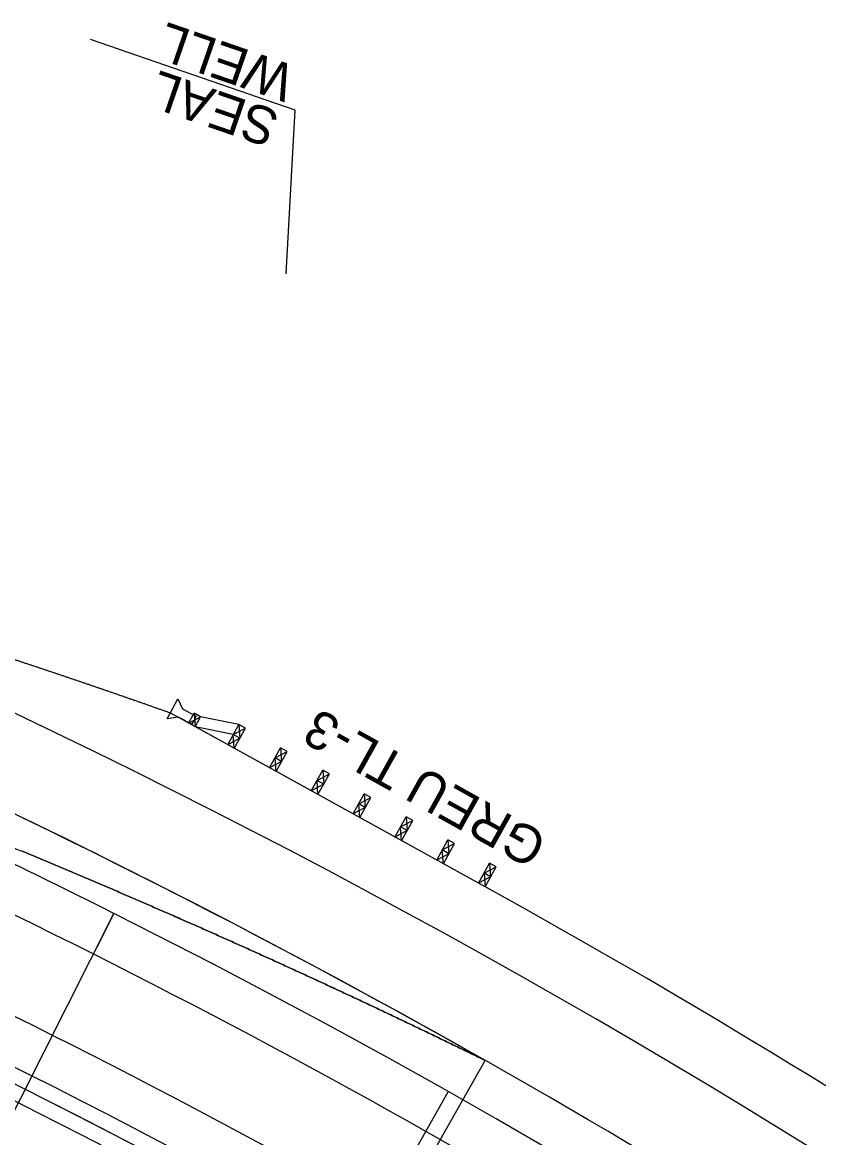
# Model space of a CAD drawing. Extents: x 472216 to 481979, y 489069 to 507339.
# Drawn here: x 480620.5 to 480725.5, y 493203.9 to 493351.1 of the extents above; entities that cross this region are included whole.
import ezdxf

# ---------------------------------------------------------------- set-up
doc = ezdxf.new("R2010")
doc.units = 0
for name, color, linetype in [('Exist Structure Minor Pipes HDPE 12 Inch Text', 7, 'Continuous'), ('Prop Drainage Structure Pipe CSP 15in', 7, 'Continuous'), ('Prop Drainage Structure Pipe Plug CELL', 7, 'Continuous'), ('Prop Drainage Structure Pipe RCP 15in Class III Label', 7, 'Continuous'), ('Prop Drainage Structure Pipe RCP 24in Class III Label', 7, 'Continuous'), ('Prop Drainage Structure Tops and Inverts LABEL', 7, 'Continuous'), ('Prop Erosion Embankment Toe Protection CELL', 7, 'Continuous'), ('Sheet Block Revision CELL', 7, 'Continuous'), ('Sheet Clip Boundary CELL', 7, 'Continuous'), ('Sheet North Arrow Point CELL', 7, 'Continuous'), ('Sheet PE Seal Cell', 7, 'Continuous')]:
    doc.layers.add(name, color=color, linetype=linetype)

msp = doc.modelspace()

# ---------------------------------------------------------------- linework, layer by layer
at = {"layer": 'Exist Structure Minor Pipes HDPE 12 Inch Text'}
msp.add_arc((480155.24, 492284.78), 1036, 57.51935, 71.25998, dxfattribs=at)
at = {"layer": 'Prop Drainage Structure Pipe Plug CELL'}
for p, q in [((480639.59, 493259.17), (480640.97, 493261.77)), ((480640.97, 493261.77), (480641.61, 493260.46)), ((480641.61, 493260.46), (480643.42, 493259.51)), ((480642.4, 493258.59), (480643.13, 493259.9)), ((480644, 493259.42), (480643.13, 493259.9)), ((480643.13, 493259.9), (480643.28, 493258.1)), ((480641.04, 493259.38), (480639.59, 493259.17)), ((480642.85, 493258.43), (480641.04, 493259.38)), ((480642.4, 493258.59), (480644, 493259.42)), ((480683.76, 493235.74), (480642.84, 493258.34)), ((480643.13, 493258.97), (480642.85, 493258.43)), ((480643.42, 493259.51), (480643.13, 493258.97)), ((480643.28, 493258.1), (480644, 493259.42)), ((480644, 493259.42), (480643.56, 493259.66)), ((480649.05, 493258.42), (480644, 493259.42)), ((480647.57, 493255.73), (480649.05, 493258.42)), ((480649.92, 493257.93), (480649.05, 493258.42)), ((480649.05, 493258.42), (480649.18, 493256.59)), ((480648.31, 493257.07), (480643.28, 493258.1)), ((480648.31, 493257.07), (480649.92, 493257.93)), ((480649.18, 493256.59), (480648.31, 493257.07)), ((480648.44, 493255.25), (480648.31, 493257.07)), ((480648.44, 493255.25), (480649.92, 493257.93)), ((480649.18, 493256.59), (480647.57, 493255.73)), ((480653.08, 493252.69), (480654.53, 493255.31)), ((480653.81, 493254), (480655.41, 493254.83)), ((480654.68, 493253.52), (480653.81, 493254)), ((480653.96, 493252.2), (480653.81, 493254)), ((480653.96, 493252.2), (480655.41, 493254.83)), ((480655.41, 493254.83), (480654.53, 493255.31)), ((480654.53, 493255.31), (480654.68, 493253.52)), ((480654.68, 493253.52), (480653.08, 493252.69)), ((480658.6, 493249.64), (480660.12, 493252.39)), ((480659.36, 493251.01), (480660.99, 493251.9)), ((480660.23, 493250.53), (480659.36, 493251.01)), ((480659.47, 493249.16), (480659.36, 493251.01)), ((480659.47, 493249.16), (480660.99, 493251.9)), ((480660.99, 493251.9), (480660.12, 493252.39)), ((480660.12, 493252.39), (480660.23, 493250.53)), ((480660.23, 493250.53), (480658.6, 493249.64)), ((480664.11, 493246.59), (480665.58, 493249.25)), ((480664.85, 493247.92), (480666.46, 493248.77)), ((480664.99, 493246.11), (480666.46, 493248.77)), ((480666.46, 493248.77), (480665.58, 493249.25)), ((480665.58, 493249.25), (480665.72, 493247.44)), ((480665.72, 493247.44), (480664.11, 493246.59)), ((480664.99, 493246.11), (480664.11, 493246.59)), ((480665.72, 493247.44), (480664.85, 493247.92)), ((480664.99, 493246.11), (480664.85, 493247.92)), ((480669.63, 493243.55), (480671.1, 493246.22)), ((480670.37, 493244.88), (480671.98, 493245.73)), ((480670.51, 493243.06), (480671.98, 493245.73)), ((480671.98, 493245.73), (480671.1, 493246.22)), ((480671.1, 493246.22), (480671.24, 493244.4)), ((480671.24, 493244.4), (480669.63, 493243.55)), ((480671.24, 493244.4), (480670.37, 493244.88)), ((480670.51, 493243.06), (480670.37, 493244.88)), ((480675.15, 493240.5), (480676.62, 493243.17)), ((480675.88, 493241.84), (480677.5, 493242.69)), ((480676.02, 493240.02), (480677.5, 493242.69)), ((480677.5, 493242.69), (480676.62, 493243.17)), ((480676.62, 493243.17), (480676.76, 493241.35)), ((480676.76, 493241.35), (480675.15, 493240.5)), ((480676.76, 493241.35), (480675.88, 493241.84)), ((480676.02, 493240.02), (480675.88, 493241.84)), ((480680.66, 493237.46), (480682.11, 493240.08)), ((480681.39, 493238.77), (480682.99, 493239.6)), ((480681.54, 493236.97), (480682.99, 493239.6)), ((480682.99, 493239.6), (480682.11, 493240.08)), ((480682.11, 493240.08), (480682.26, 493238.29)), ((480680.66, 493237.46), (480681.39, 493238.77)), ((480682.26, 493238.29), (480680.66, 493237.46)), ((480682.26, 493238.29), (480681.39, 493238.77)), ((480681.39, 493238.77), (480681.54, 493236.97)), ((480681.54, 493236.97), (480680.66, 493237.46))]:
    msp.add_line(p, q, dxfattribs=at)
at = {"layer": 'Prop Drainage Structure Pipe RCP 15in Class III Label'}
for radius, start, end in [(1066, 50.82715, 71.26622), (1066, 60.45413, 71.26607), (1054, 50.82715, 71.26622)]:
    msp.add_arc((480155.89, 492286.67), radius, start, end, dxfattribs=at)
for points in [[(480599.82, 493249.96), (480600.36, 493249.75), (480601.2, 493249.43), (480602.04, 493249.1), (480602.88, 493248.77), (480603.72, 493248.43), (480604.56, 493248.1), (480605.4, 493247.77), (480606.24, 493247.44), (480607.08, 493247.1), (480607.92, 493246.77), (480608.76, 493246.43), (480609.6, 493246.1), (480610.43, 493245.76), (480611.27, 493245.42), (480612.11, 493245.08), (480612.95, 493244.74), (480613.79, 493244.4), (480614.62, 493244.06), (480615.46, 493243.72), (480616.3, 493243.38), (480617.13, 493243.03), (480617.97, 493242.69), (480618.8, 493242.35), (480619.64, 493242), (480620.48, 493241.66)], [(480681.55, 493214.05), (480680.74, 493214.45), (480679.92, 493214.85), (480679.11, 493215.24), (480678.29, 493215.64), (480677.47, 493216.04), (480676.66, 493216.43), (480675.84, 493216.83), (480675.02, 493217.22), (480674.21, 493217.62), (480673.39, 493218.01), (480672.57, 493218.4), (480671.75, 493218.79), (480670.93, 493219.18), (480670.12, 493219.57), (480669.3, 493219.96), (480668.48, 493220.35), (480667.66, 493220.74), (480666.84, 493221.13), (480666.02, 493221.51), (480665.2, 493221.9), (480664.38, 493222.28), (480663.55, 493222.67), (480662.73, 493223.05), (480661.91, 493223.43), (480661.09, 493223.82), (480660.27, 493224.2), (480659.44, 493224.58), (480658.62, 493224.96), (480657.8, 493225.34), (480656.98, 493225.72), (480656.15, 493226.09), (480655.33, 493226.47), (480654.5, 493226.85), (480653.68, 493227.22), (480652.85, 493227.6), (480652.03, 493227.97), (480651.2, 493228.35), (480650.38, 493228.72), (480649.55, 493229.09), (480648.73, 493229.46), (480647.9, 493229.83), (480647.07, 493230.2), (480646.25, 493230.57), (480645.42, 493230.94), (480644.59, 493231.31), (480643.76, 493231.68), (480642.93, 493232.04), (480642.11, 493232.41), (480641.28, 493232.77), (480640.45, 493233.14), (480639.62, 493233.5), (480638.79, 493233.86), (480637.96, 493234.22), (480637.13, 493234.58), (480636.3, 493234.95), (480635.47, 493235.31), (480634.64, 493235.66), (480633.81, 493236.02), (480632.98, 493236.38), (480632.15, 493236.74), (480631.31, 493237.09), (480630.48, 493237.45), (480629.65, 493237.8), (480628.82, 493238.16), (480627.98, 493238.51), (480627.15, 493238.86), (480626.32, 493239.21), (480625.48, 493239.57), (480624.65, 493239.92), (480623.82, 493240.26), (480622.98, 493240.61), (480622.15, 493240.96), (480621.31, 493241.31), (480620.48, 493241.66)], [(480620.48, 493241.66), (480621.31, 493241.31), (480622.15, 493240.96), (480622.98, 493240.61), (480623.82, 493240.26), (480624.65, 493239.92), (480625.48, 493239.57), (480626.32, 493239.21), (480627.15, 493238.86), (480627.98, 493238.51), (480628.82, 493238.16), (480629.65, 493237.8), (480630.48, 493237.45), (480631.31, 493237.09), (480632.15, 493236.74), (480632.98, 493236.38), (480633.81, 493236.02), (480634.64, 493235.66), (480635.47, 493235.31), (480636.3, 493234.95), (480637.13, 493234.58), (480637.96, 493234.22), (480638.79, 493233.86), (480639.62, 493233.5), (480640.45, 493233.14), (480641.03, 493232.88)], [(480641.03, 493232.88), (480641.28, 493232.77), (480642.11, 493232.41), (480642.93, 493232.04), (480643.76, 493231.68), (480644.59, 493231.31), (480645.42, 493230.94), (480646.25, 493230.57), (480647.07, 493230.2), (480647.9, 493229.83), (480648.73, 493229.46), (480649.55, 493229.09), (480650.38, 493228.72), (480651.2, 493228.35), (480652.03, 493227.97), (480652.85, 493227.6), (480653.68, 493227.22), (480654.5, 493226.85), (480655.33, 493226.47), (480656.15, 493226.09), (480656.98, 493225.72), (480657.8, 493225.34), (480658.62, 493224.96), (480659.44, 493224.58), (480660.27, 493224.2), (480661.09, 493223.82), (480661.39, 493223.68)], [(480661.39, 493223.68), (480661.91, 493223.43), (480662.73, 493223.05), (480663.55, 493222.67), (480664.38, 493222.28), (480665.2, 493221.9), (480666.02, 493221.51), (480666.84, 493221.13), (480667.66, 493220.74), (480668.48, 493220.35), (480669.3, 493219.96), (480670.12, 493219.57), (480670.93, 493219.18), (480671.75, 493218.79), (480672.57, 493218.4), (480673.39, 493218.01), (480674.21, 493217.62), (480675.02, 493217.22), (480675.84, 493216.83), (480676.66, 493216.43), (480677.47, 493216.04), (480678.29, 493215.64), (480679.11, 493215.24), (480679.92, 493214.85), (480680.74, 493214.45), (480681.55, 493214.05)]]:
    msp.add_spline(points, degree=3, dxfattribs=at)
at = {"layer": 'Prop Drainage Structure Pipe RCP 24in Class III Label'}
for radius, start, end in [(1078, 51.63222, 71.28205), (1042, 50.82715, 71.25998)]:
    msp.add_arc((480155.89, 492286.67), radius, start, end, dxfattribs=at)
at = {"layer": 'Prop Drainage Structure Tops and Inverts LABEL'}
for radius, start, end in [(1032, 47.5792, 71.2674), (1086, 51.63222, 60.91713)]:
    msp.add_arc((480155.89, 492286.67), radius, start, end, dxfattribs=at)
at = {"layer": 'Prop Erosion Embankment Toe Protection CELL'}
msp.add_line((480683.76, 493235.74), (480639.99, 493259.92), dxfattribs=at)
for radius, start, end in [(1036, 57.49364, 71.25998), (1086, 51.63222, 60.91713)]:
    msp.add_arc((480155.89, 492286.67), radius, start, end, dxfattribs=at)
msp.add_spline([(480639.99, 493259.92), (480639.57, 493260.07), (480639.15, 493260.22), (480638.72, 493260.36), (480638.3, 493260.51), (480637.88, 493260.66), (480637.46, 493260.81), (480637.04, 493260.96), (480636.62, 493261.11), (480636.2, 493261.25), (480635.77, 493261.4), (480635.35, 493261.55), (480634.93, 493261.69), (480634.51, 493261.84), (480634.09, 493261.99), (480633.67, 493262.13), (480633.24, 493262.28), (480632.82, 493262.43), (480632.4, 493262.57), (480631.98, 493262.72), (480631.56, 493262.86), (480631.14, 493263.01), (480630.71, 493263.15), (480630.29, 493263.3), (480629.87, 493263.44), (480629.45, 493263.59), (480629.03, 493263.73), (480628.6, 493263.88), (480628.18, 493264.02), (480627.76, 493264.17), (480627.34, 493264.31), (480626.91, 493264.45), (480626.49, 493264.6), (480626.07, 493264.74), (480625.65, 493264.88), (480625.22, 493265.03), (480624.8, 493265.17), (480624.38, 493265.31), (480623.96, 493265.45), (480623.53, 493265.59), (480623.11, 493265.74), (480622.69, 493265.88), (480622.27, 493266.02), (480621.84, 493266.16), (480621.42, 493266.3), (480621, 493266.44), (480620.57, 493266.58), (480620.15, 493266.72), (480619.73, 493266.87), (480619.31, 493267.01), (480618.88, 493267.15), (480618.46, 493267.29), (480618.04, 493267.43), (480617.61, 493267.56), (480617.19, 493267.7), (480616.77, 493267.84), (480616.34, 493267.98), (480615.92, 493268.12), (480615.5, 493268.26), (480615.07, 493268.4), (480614.65, 493268.54), (480614.23, 493268.67), (480613.8, 493268.81), (480613.38, 493268.95), (480612.96, 493269.09), (480612.53, 493269.23), (480612.11, 493269.36), (480611.68, 493269.5), (480611.26, 493269.64), (480610.84, 493269.77), (480610.41, 493269.91), (480609.99, 493270.05), (480609.57, 493270.18), (480608.72, 493270.45)], degree=3, dxfattribs=at)
at = {"layer": 'Sheet Block Revision CELL'}
for p, q in [((480656.47, 493339.5), (480629.48, 493348.83)), ((480655.3, 493317.9), (480656.47, 493339.5)), ((480635.53, 493132.86), (480681.55, 493214.05))]:
    msp.add_line(p, q, dxfattribs=at)
msp.add_arc((480120.75, 492209.98), 1060, 51.97314, 70.88636, dxfattribs=at)
at = {"layer": 'Sheet Clip Boundary CELL'}
for p, q in [((480542.61, 493054.81), (480632.54, 493233.45)), ((480578.4, 493035.72), (480676.65, 493209.92))]:
    msp.add_line(p, q, dxfattribs=at)
msp.add_arc((480155.89, 492286.67), 1034, 50.82715, 71.25998, dxfattribs=at)
at = {"layer": 'Sheet North Arrow Point CELL'}
msp.add_arc((480155.89, 492286.67), 1060, 12.98112, 71.78843, dxfattribs=at)
msp.add_arc((480155.89, 492286.67), 1060, 12.98112, 71.78843, dxfattribs=at)
at = {"layer": 'Sheet PE Seal Cell'}
msp.add_line((480632.54, 493233.45), (480630.29, 493228.99), dxfattribs=at)

# ---------------------------------------------------------------- texts
at = {"layer": 'Prop Drainage Structure Pipe CSP 15in'}
for s, p in [('WELL', (480656.72, 493345.24)), ('SEAL', (480654.65, 493339.24))]:
    msp.add_text(s, height=5, rotation=160.9892, dxfattribs=at).set_placement(p)
at = {"layer": 'Prop Drainage Structure Pipe Plug CELL'}
msp.add_text('GREU TL-3', height=5, rotation=150.8507, dxfattribs=at).set_placement((480690.03, 493243.62))

doc.saveas('drawing.dxf')
